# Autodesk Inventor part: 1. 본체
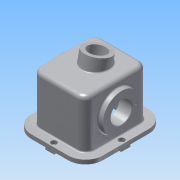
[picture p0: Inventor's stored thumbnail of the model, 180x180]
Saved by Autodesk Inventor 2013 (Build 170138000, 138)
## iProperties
Created: 2014-11
Part Number: 1. 본체
Material: 알루미늄 6061
Document SubType Name: Modeling
Designer: Administrator
Density: 1 g/cm^3
Author: Administrator
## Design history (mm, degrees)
sketch "스케치1"
  geometry: L1 (-45, 98)-(45, 98); L2 (87, 56)-(87, -56); L3 (45, -98)-(-45, -98); L4 (-87, -56)-(-87, 56); A1 r 42 centre (-45, 56) between (-45, 98) and (-87, 56); A2 r 42 centre (45, 56) between (87, 56) and (45, 98); A3 r 42 centre (45, -56) between (45, -98) and (87, -56); A4 r 42 centre (-45, -56) between (-87, -56) and (-45, -98); 1 further point
  constraints: 8 end point, 8 point on circle, 8 tangent, 4 centre point, 3 equal radius, 2 parallel, 1 horizontal, 1 perpendicular
extrude "돌출1" new body sketch "스케치1" distance "d3" = 10; taper "d4" = 0 deg
sketch "스케치2"
  geometry: L1 (-11, 78)-(11, 78); L2 (67, 11)-(67, -11); L3 (11, -78)-(-11, -78); L4 (-67, -11)-(-67, 11); L5 (11, 98)-(11, 78); L6 (-11, 98)-(-11, 78); L7 (-87, 11)-(-67, 11); L8 (-87, -11)-(-67, -11); L9 (-11, -78)-(-11, -98); L10 (11, -78)-(11, -98); L11 (67, 11)-(87, 11); L12 (67, -11)-(87, -11); L13 (-11, 98)-(11, 98); L14 (87, 11)-(87, -11); L15 (-87, 11)-(-87, -11); L16 (-11, -98)-(11, -98); 4 further points
  constraints: 32 end point, 3 perpendicular, 1 parallel
extrude "돌출2" join sketch "스케치2" distance "d11" = 5; taper "d12" = 0 deg
sketch "스케치3"
  geometry: L1 (-45, 76)-(45, 76); L2 (65, 56)-(65, -56); L3 (45, -76)-(-45, -76); L4 (-65, -56)-(-65, 56); A1 r 20 centre (-45, 56) between (-45, 76) and (-65, 56); A2 r 20 centre (45, 56) between (65, 56) and (45, 76); A3 r 20 centre (45, -56) between (45, -76) and (65, -56); A4 r 20 centre (-45, -56) between (-65, -56) and (-45, -76); 1 further point
  constraints: 8 end point, 8 point on circle, 8 tangent, 4 centre point, 3 equal radius, 2 parallel, 1 horizontal, 1 perpendicular
extrude "돌출3" join sketch "스케치3" distance "d16" = 118; taper "d17" = 0 deg
node "작업 평면1"
sketch "스케치4"
  geometry: L1 (-58, 56)-(-142.121, 73.88) reference; L2 (-118, 37.061)-(-148.566, 43.558); L3 (-148.566, 43.558)-(-142.121, 73.88); L4 (-118, 37.061)-(-111.555, 67.383)
  constraints: 8 end point, 2 perpendicular, 1 parallel, 1 point on line, 1 other
revolve "회전1" sketch "스케치4" stored, may be unused: angle "d23" = 90 deg
sketch "스케치5"
  geometry: L1 (-45, 66)-(45, 66); L2 (55, 56)-(55, -56); L3 (45, -66)-(-45, -66); L4 (-55, -56)-(-55, 56); A1 r 10 centre (45, 56) between (55, 56) and (45, 66); A2 r 10 centre (45, -56) between (45, -66) and (55, -56); A3 r 10 centre (-45, -56) between (-55, -56) and (-45, -66); A4 r 10 centre (-45, 56) between (-45, 66) and (-55, 56)
  constraints: 8 end point, 8 point on circle, 4 centre point
extrude "돌출4" cut sketch "스케치5" distance "d25" = 118; taper "d26" = 0 deg
sketch "스케치6"
  geometry: C1 r 45.5 at (-58, 56)
  constraints: 1 centre point
extrude "돌출5" join sketch "스케치6" distance "d29" = 12; taper "d30" = 0 deg
sketch "스케치7"
  geometry: C1 r 45.5 at (58, 56) reference
extrude "돌출6" join sketch "스케치7" distance "d31" = 12; taper "d32" = 0 deg
sketch "스케치8"
  geometry: C1 r 45.5 at (-68, 56) reference; 1 further point
extrude "돌출7" join sketch "스케치8" distance "d33" = 10; taper "d34" = -45 deg
sketch "스케치9"
  geometry: C1 r 45.5 at (68, 56) reference; 1 further point
extrude "돌출8" join sketch "스케치9" distance "d35" = 10; taper "d36" = -45 deg
sketch "스케치10"
  geometry: C1 r 26 at (0, 0); 1 further point
  constraints: 1 centre point
  dimensions: "d37" = 52 diameter of C1
extrude "돌출9" cut sketch "스케치10" stored distance "d38" = 10; taper "d39" = 0 deg
sketch "스케치11"
  geometry: L1 (-94.267, 63.709)-(-142.121, 73.88) reference; L2 (-108, 0)-(-108, 112) reference; L3 (-122.033, 48.142)-(-146.487, 53.339); L4 (-97.385, 49.036)-(-120.786, 54.01); L5 (-120.786, 54.01)-(-122.033, 48.142); L6 (-146.487, 53.339)-(-142.121, 73.88); L7 (-97.385, 49.036)-(-94.267, 63.709); 1 further point
  constraints: 12 end point, 4 parallel, 1 other
revolve "회전2" sketch "스케치11" stored, may be unused: angle "d45" = 90 deg
fillet "모깎기1" dims "d46" = 10
fillet "모깎기2" dims "d47" = 3
chamfer "모따기1" distance "d48" = 1; stored, may be unused: second distance "d49" = 2, angle "d50" = 45 deg
chamfer "모따기2" distance "d51" = 1; stored, may be unused: second distance "d52" = 2, angle "d53" = 45 deg
chamfer "모따기3" distance "d54" = 1; stored, may be unused: second distance "d55" = 2, angle "d56" = 45 deg
chamfer "모따기4" distance "d57" = 1; stored, may be unused: second distance "d58" = 2, angle "d59" = 45 deg
fillet "모깎기3" dims "d60" = 0.3
sketch "스케치12"
  geometry: L1 (88.505, 11.432)-(1.495, 11.432); L2 (1.495, 11.432)-(1.495, 40.568); L3 (1.495, 40.568)-(88.505, 40.568); L4 (88.505, 40.568)-(88.505, 11.432); 1 further point
  constraints: 2 other
extrude "돌출10" join sketch "스케치12" distance "d64" = 1; taper "d65" = 0 deg
sketch "스케치13"
  geometry: 7 further points
hole "구멍1" sketch "스케치13" at (0, 88), (77, 0), (-77, 0), (0, -88) diameter "d67" = 9; stored, may be unused: countersink angle "d71" = 90 deg, drill point angle "d73" = 118 deg; dims "d68" = 6, "d69" = 14, "d70" = 8.6, "d72" = 8
sketch "스케치14"
  geometry: 6 further points
  constraints: 5 other
  dimensions: "d77" = 360 deg dimension on point (0, 0) point (0, 35) (derived)
hole "구멍2" sketch "스케치14" at (0, 35), (-35, 0), (0, -35), (35, 0) diameter "d79" = 3.242; stored, may be unused: countersink angle "d83" = 90 deg, drill point angle "d85" = 118 deg; dims "d80" = 13, "d81" = 14, "d82" = 8.6, "d84" = 16
sketch "스케치15"
  geometry: 6 further points
  constraints: 5 other
  dimensions: "d89" = 360 deg dimension on point (0, 0) point (0, 35) (derived)
hole "구멍3" sketch "스케치15" at (0, 35), (-35, 0), (0, -35), (35, 0) diameter "d91" = 3.242; stored, may be unused: countersink angle "d95" = 90 deg, drill point angle "d97" = 118 deg; dims "d92" = 13, "d93" = 14, "d94" = 8.6, "d96" = 16
node "솔리드1"
other parameters: "d6" = 11, "d8" = 11, "d9" = 11, "d10" = 11
